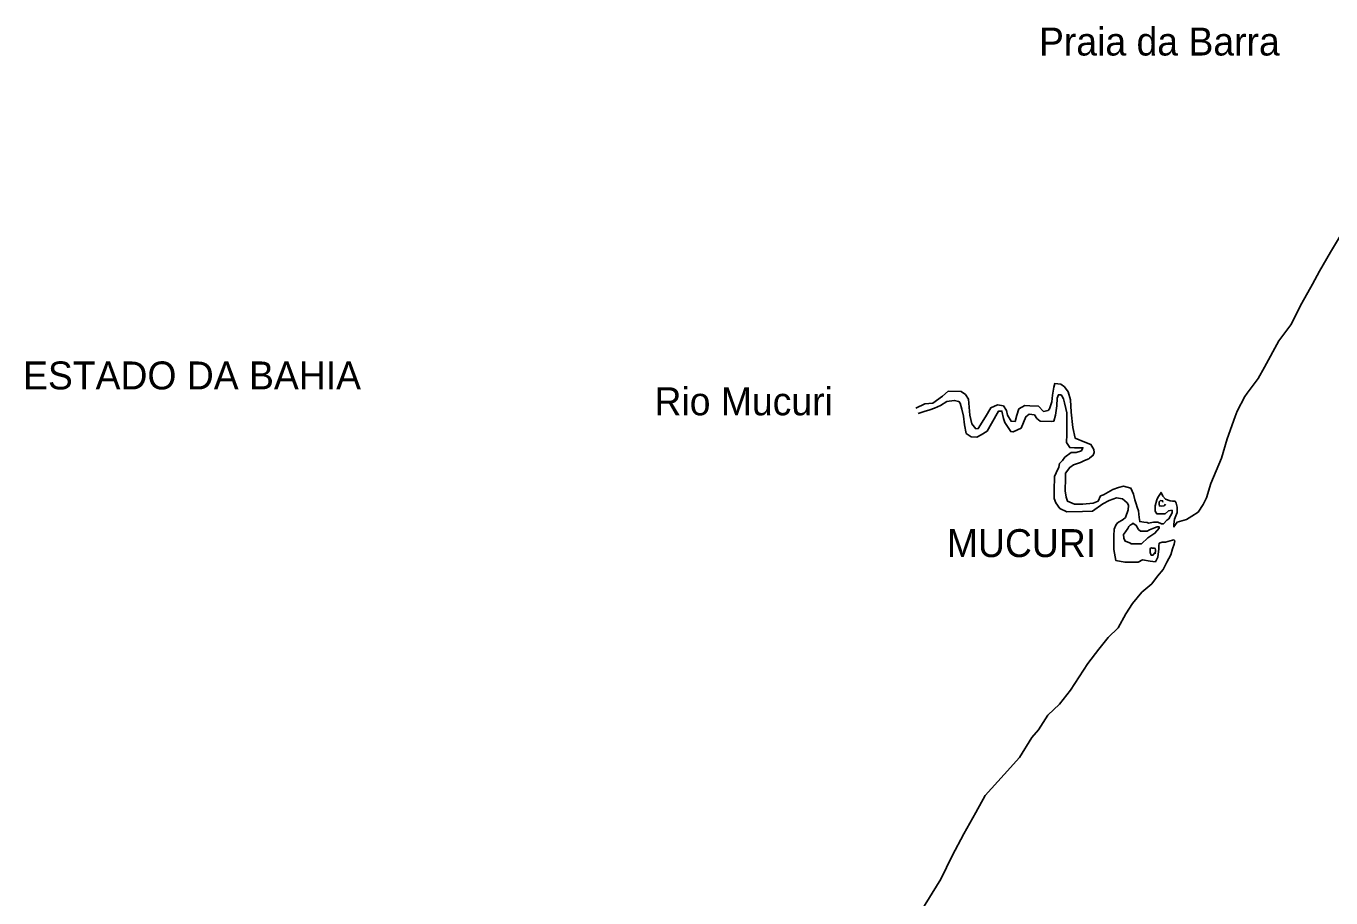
# Model space of a CAD drawing. Extents: x 662444 to 1640468, y 7452018 to 9606170.
# Drawn here: x 1050221 to 1080709, y 7982275 to 8002639 of the extents above; entities that cross this region are included whole.
import ezdxf

# ---------------------------------------------------------------- set-up
doc = ezdxf.new("R2010")
doc.units = 0
doc.layers.add('Level 1', color=7, linetype='Continuous')
doc.layers.add('Level 3', color=7, linetype='Continuous')

msp = doc.modelspace()

# ---------------------------------------------------------------- linework, layer by layer
at = {"layer": 'Level 1'}
for points in [[(1075328, 7991666), (1075398, 7991688), (1075555, 7991783), (1075617, 7991811), (1075742, 7991862), (1075866, 7991890), (1076035, 7991846), (1076100, 7991704), (1076127, 7991572), (1076162, 7991478), (1076183, 7991400), (1076212, 7991315), (1076217, 7991237), (1076230, 7991160), (1076243, 7991066), (1076335, 7991055), (1076419, 7991045), (1076450, 7991029), (1076566, 7991049), (1076666, 7991053), (1076750, 7991012), (1076796, 7991011), (1076876, 7991101), (1076924, 7991130), (1076997, 7991267), (1076999, 7991329), (1076913, 7991316), (1076835, 7991249), (1076703, 7991246), (1076641, 7991248), (1076605, 7991310), (1076601, 7991433), (1076643, 7991572), (1076668, 7991625), (1076741, 7991746), (1076778, 7991660), (1076845, 7991588), (1076951, 7991546), (1077005, 7991545), (1077067, 7991543), (1077096, 7991495), (1077117, 7991402), (1077113, 7991279), (1077054, 7991119), (1077042, 7991003), (1077040, 7990941), (1077114, 7991055), (1077331, 7991117), (1077457, 7991191), (1077606, 7991287), (1077727, 7991461), (1077801, 7991621), (1077905, 7991957), (1078154, 7992544), (1078283, 7992996), (1078469, 7993516), (1078519, 7993646), (1078699, 7993989), (1078755, 7994064), (1079013, 7994404), (1079159, 7994670), (1079494, 7995284), (1079776, 7995663), (1080030, 7996164), (1080276, 7996613), (1080446, 7996917), (1080700, 7997357), (1080935, 7997751)], [(1071009, 7993715), (1071220, 7993817), (1071406, 7993834), (1071635, 7993997), (1071769, 7994108), (1072070, 7994107), (1072167, 7994034), (1072242, 7993924), (1072269, 7993552), (1072316, 7993350), (1072414, 7993231), (1072467, 7993238), (1072638, 7993511), (1072760, 7993723), (1072916, 7993796), (1073055, 7993768), (1073128, 7993657), (1073155, 7993549), (1073236, 7993407), (1073329, 7993405), (1073371, 7993550), (1073415, 7993696), (1073555, 7993776), (1073671, 7993772), (1073879, 7993759), (1073992, 7993639), (1074099, 7993659), (1074131, 7993697), (1074191, 7993865), (1074204, 7994019), (1074232, 7994203), (1074257, 7994288), (1074327, 7994286), (1074396, 7994276), (1074487, 7994211), (1074568, 7994093), (1074624, 7993906), (1074638, 7993620), (1074682, 7993263), (1074736, 7993013), (1074957, 7992921), (1075102, 7992863), (1075167, 7992745), (1075180, 7992676), (1075156, 7992614), (1075069, 7992548), (1075053, 7992533), (1074952, 7992489), (1074858, 7992446), (1074694, 7992389), (1074608, 7992330), (1074510, 7992194), (1074507, 7992077), (1074498, 7991784), (1074525, 7991637), (1074553, 7991544), (1074720, 7991469), (1074913, 7991471), (1075153, 7991494), (1075270, 7991545), (1075328, 7991666)], [(1075376, 7991479), (1075139, 7991309), (1074908, 7991301), (1074538, 7991296), (1074378, 7991371), (1074282, 7991505), (1074239, 7991607), (1074244, 7991792), (1074254, 7992116), (1074287, 7992201), (1074353, 7992338), (1074371, 7992422), (1074435, 7992490), (1074492, 7992572), (1074641, 7992676), (1074756, 7992680), (1074881, 7992715), (1074906, 7992776), (1074915, 7992791), (1074714, 7992790), (1074606, 7992794), (1074532, 7992911), (1074538, 7993097), (1074541, 7993452), (1074538, 7993607), (1074518, 7993708), (1074483, 7993840), (1074463, 7993934), (1074419, 7994004), (1074404, 7994028), (1074342, 7994029), (1074316, 7993946), (1074304, 7993768), (1074274, 7993552), (1074231, 7993407), (1074170, 7993402), (1073915, 7993410), (1073840, 7993474), (1073781, 7993560), (1073658, 7993572), (1073579, 7993513), (1073471, 7993245), (1073282, 7993158), (1073229, 7993168), (1073089, 7993381), (1073061, 7993475), (1073020, 7993646), (1072943, 7993648), (1072780, 7993360), (1072674, 7993177), (1072533, 7993089), (1072439, 7993037), (1072307, 7993041), (1072186, 7993123), (1072147, 7993325), (1072122, 7993527), (1072088, 7993690), (1072045, 7993830), (1072016, 7993870), (1071909, 7993896), (1071738, 7993870), (1071589, 7993775), (1071449, 7993717), (1071339, 7993674), (1071208, 7993639), (1071067, 7993590)], [(1071125, 7981960), (1071595, 7982711), (1071858, 7983259), (1072135, 7983768), (1072413, 7984270), (1072633, 7984664), (1073072, 7985160), (1073430, 7985552), (1073722, 7986021), (1073874, 7986202), (1074093, 7986543), (1074370, 7986797), (1074628, 7987129), (1075032, 7987751), (1075288, 7988082), (1075504, 7988354), (1075736, 7988586), (1075915, 7988913), (1076076, 7989155), (1076293, 7989418), (1076523, 7989613), (1076659, 7989787), (1076787, 7989945), (1076877, 7990119), (1076967, 7990287), (1077010, 7990432), (1077044, 7990539), (1077061, 7990616), (1077039, 7990640), (1077008, 7990633), (1076845, 7990584), (1076768, 7990587), (1076697, 7990558), (1076688, 7990496), (1076686, 7990427), (1076664, 7990234), (1076607, 7990128), (1076484, 7990140), (1076307, 7990168), (1076206, 7990117), (1075890, 7990119), (1075683, 7990157), (1075636, 7990413), (1075640, 7990520), (1075637, 7990676), (1075640, 7990791), (1075641, 7990823), (1075643, 7990884), (1075685, 7990984), (1075725, 7991036), (1075858, 7991110), (1075906, 7991161), (1075973, 7991337), (1075976, 7991437), (1075969, 7991461), (1075947, 7991500), (1075843, 7991597), (1075696, 7991617), (1075525, 7991560), (1075376, 7991479)], [(1076841, 7991473), (1076809, 7991435), (1076748, 7991429), (1076701, 7991430), (1076695, 7991469), (1076696, 7991524), (1076704, 7991531), (1076728, 7991554), (1076759, 7991553), (1076774, 7991553), (1076781, 7991521)], [(1076214, 7990881), (1076259, 7990842), (1076290, 7990841), (1076413, 7990844), (1076469, 7990874), (1076585, 7990917), (1076647, 7990945), (1076694, 7990944), (1076693, 7990914), (1076597, 7990792), (1076431, 7990689), (1076280, 7990547), (1076188, 7990543), (1076149, 7990544), (1076041, 7990547), (1076011, 7990572), (1075905, 7990606), (1075869, 7990676), (1075864, 7990762), (1075911, 7990829), (1075960, 7990905), (1075984, 7990950), (1076017, 7990980), (1076071, 7991010), (1076080, 7991025), (1076162, 7990976), (1076214, 7990881)], [(1076606, 7990344), (1076550, 7990277), (1076512, 7990278), (1076483, 7990340), (1076485, 7990418), (1076485, 7990433), (1076517, 7990448), (1076540, 7990447), (1076578, 7990446), (1076601, 7990437), (1076608, 7990406), (1076607, 7990375), (1076605, 7990313)]]:
    msp.add_lwpolyline(points, dxfattribs=at)

# ---------------------------------------------------------------- texts
at = {"layer": 'Level 3'}
for s, height, p in [('Praia da Barra', 652.51, (1073888, 8001952)), ('ESTADO DA BAHIA', 652.01, (1050149, 7994153)), ('Rio Mucuri', 652.1, (1064904, 7993548)), ('MUCURI', 652.1, (1071736, 7990236))]:
    msp.add_text(s, height=height, dxfattribs=at).set_placement(p)

doc.saveas('drawing.dxf')
